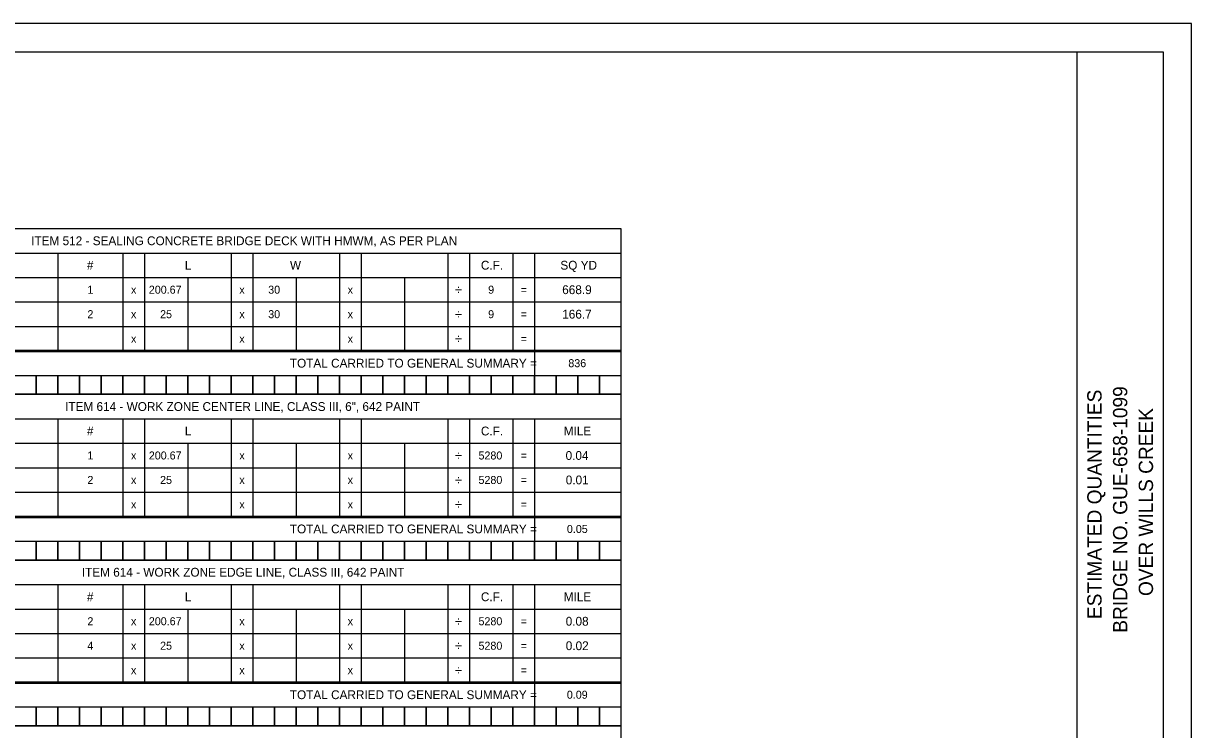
# Model space of a CAD drawing. Extents: x 0 to 34, y 0 to 22.
# Drawn here: x 13.57 to 34, y 9.65 to 22 of the extents above; entities that cross this region are included whole.
import ezdxf

# ---------------------------------------------------------------- set-up
doc = ezdxf.new("R2010")
doc.units = 0
for name, color, linetype in [('Default', 7, 'Continuous'), ('SH_Border', 7, 'Continuous'), ('SH_Cut_Line', 7, 'Continuous'), ('SH_Data', 7, 'Continuous')]:
    doc.layers.add(name, color=color, linetype=linetype)

msp = doc.modelspace()

# ---------------------------------------------------------------- linework, layer by layer
at = {"layer": 'Default'}
for p, q in [((10.763, 18.412), (24.021, 18.412)), ((24.021, 18.412), (24.021, 16.26)), ((10.763, 17.984), (24.021, 17.984)), ((14.172, 17.984), (14.172, 16.282)), ((15.308, 17.984), (15.308, 16.282)), ((15.687, 17.984), (15.687, 16.282)), ((17.203, 17.984), (17.203, 16.282)), ((17.581, 17.984), (17.581, 16.282)), ((19.097, 17.984), (19.097, 16.282)), ((19.476, 17.984), (19.476, 16.282)), ((20.991, 17.984), (20.991, 16.282)), ((21.37, 17.984), (21.37, 16.282)), ((22.127, 17.984), (22.127, 16.282)), ((22.506, 17.984), (22.506, 16.282)), ((10.763, 17.556), (24.021, 17.556)), ((16.445, 17.556), (16.445, 16.282)), ((18.339, 17.556), (18.339, 16.282)), ((20.233, 17.556), (20.233, 16.282)), ((10.763, 17.128), (24.021, 17.128)), ((10.763, 16.699), (24.021, 16.699)), ((10.763, 16.282), (24.021, 16.282)), ((10.763, 16.26), (24.021, 16.26)), ((22.506, 16.26), (22.506, 15.843)), ((24.021, 16.282), (24.021, 13.361)), ((10.763, 15.843), (24.021, 15.843)), ((10.763, 15.514), (24.021, 15.514)), ((10.763, 15.085), (24.021, 15.085)), ((14.172, 15.085), (14.172, 13.383)), ((15.308, 15.085), (15.308, 13.383)), ((15.687, 15.085), (15.687, 13.383)), ((17.203, 15.085), (17.203, 13.383)), ((17.581, 15.085), (17.581, 13.383)), ((19.097, 15.085), (19.097, 13.383)), ((19.476, 15.085), (19.476, 13.383)), ((20.991, 15.085), (20.991, 13.383)), ((21.37, 15.085), (21.37, 13.383)), ((22.127, 15.085), (22.127, 13.383)), ((22.506, 15.085), (22.506, 13.383)), ((10.763, 14.657), (24.021, 14.657)), ((16.445, 14.657), (16.445, 13.383)), ((18.339, 14.657), (18.339, 13.383)), ((20.233, 14.657), (20.233, 13.383)), ((10.763, 14.229), (24.021, 14.229)), ((10.763, 13.801), (24.021, 13.801)), ((10.763, 13.383), (24.021, 13.383)), ((10.763, 13.361), (24.021, 13.361)), ((22.506, 13.361), (22.506, 12.944)), ((24.021, 13.383), (24.021, 10.463)), ((10.763, 12.944), (24.021, 12.944)), ((10.763, 12.615), (24.021, 12.615)), ((10.763, 12.187), (24.021, 12.187)), ((14.172, 12.187), (14.172, 10.485)), ((15.308, 12.187), (15.308, 10.485)), ((15.687, 12.187), (15.687, 10.485)), ((17.203, 12.187), (17.203, 10.485)), ((17.581, 12.187), (17.581, 10.485)), ((19.097, 12.187), (19.097, 10.485)), ((19.476, 12.187), (19.476, 10.485)), ((20.991, 12.187), (20.991, 10.485)), ((21.37, 12.187), (21.37, 10.485)), ((22.127, 12.187), (22.127, 10.485)), ((22.506, 12.187), (22.506, 10.485)), ((10.763, 11.758), (24.021, 11.758)), ((16.445, 11.758), (16.445, 10.485)), ((18.339, 11.758), (18.339, 10.485)), ((20.233, 11.758), (20.233, 10.485)), ((10.763, 11.33), (24.021, 11.33)), ((10.763, 10.902), (24.021, 10.902)), ((10.763, 10.485), (24.021, 10.485)), ((10.763, 10.463), (24.021, 10.463)), ((22.506, 10.463), (22.506, 10.045)), ((24.021, 10.485), (24.021, 7.564)), ((10.763, 10.045), (24.021, 10.045)), ((10.763, 9.716), (24.021, 9.716))]:
    msp.add_line(p, q, dxfattribs=at)
for points in [[(13.414, 15.843), (13.793, 15.843), (13.793, 15.514), (13.414, 15.514)], [(13.793, 15.843), (14.172, 15.843), (14.172, 15.514), (13.793, 15.514)], [(14.172, 15.843), (14.551, 15.843), (14.551, 15.514), (14.172, 15.514)], [(14.551, 15.843), (14.93, 15.843), (14.93, 15.514), (14.551, 15.514)], [(14.93, 15.843), (15.308, 15.843), (15.308, 15.514), (14.93, 15.514)], [(15.308, 15.843), (15.687, 15.843), (15.687, 15.514), (15.308, 15.514)], [(15.687, 15.843), (16.066, 15.843), (16.066, 15.514), (15.687, 15.514)], [(16.066, 15.843), (16.445, 15.843), (16.445, 15.514), (16.066, 15.514)], [(16.445, 15.843), (16.824, 15.843), (16.824, 15.514), (16.445, 15.514)], [(16.824, 15.843), (17.203, 15.843), (17.203, 15.514), (16.824, 15.514)], [(17.203, 15.843), (17.581, 15.843), (17.581, 15.514), (17.203, 15.514)], [(17.581, 15.843), (17.96, 15.843), (17.96, 15.514), (17.581, 15.514)], [(17.96, 15.843), (18.339, 15.843), (18.339, 15.514), (17.96, 15.514)], [(18.339, 15.843), (18.718, 15.843), (18.718, 15.514), (18.339, 15.514)], [(18.718, 15.843), (19.097, 15.843), (19.097, 15.514), (18.718, 15.514)], [(19.097, 15.843), (19.476, 15.843), (19.476, 15.514), (19.097, 15.514)], [(19.476, 15.843), (19.854, 15.843), (19.854, 15.514), (19.476, 15.514)], [(19.854, 15.843), (20.233, 15.843), (20.233, 15.514), (19.854, 15.514)], [(20.233, 15.843), (20.612, 15.843), (20.612, 15.514), (20.233, 15.514)], [(20.612, 15.843), (20.991, 15.843), (20.991, 15.514), (20.612, 15.514)], [(20.991, 15.843), (21.37, 15.843), (21.37, 15.514), (20.991, 15.514)], [(21.37, 15.843), (21.748, 15.843), (21.748, 15.514), (21.37, 15.514)], [(21.748, 15.843), (22.127, 15.843), (22.127, 15.514), (21.748, 15.514)], [(22.127, 15.843), (22.506, 15.843), (22.506, 15.514), (22.127, 15.514)], [(22.506, 15.843), (22.885, 15.843), (22.885, 15.514), (22.506, 15.514)], [(22.885, 15.843), (23.264, 15.843), (23.264, 15.514), (22.885, 15.514)], [(23.264, 15.843), (23.643, 15.843), (23.643, 15.514), (23.264, 15.514)], [(23.643, 15.843), (24.021, 15.843), (24.021, 15.514), (23.643, 15.514)], [(13.414, 12.944), (13.793, 12.944), (13.793, 12.615), (13.414, 12.615)], [(13.793, 12.944), (14.172, 12.944), (14.172, 12.615), (13.793, 12.615)], [(14.172, 12.944), (14.551, 12.944), (14.551, 12.615), (14.172, 12.615)], [(14.551, 12.944), (14.93, 12.944), (14.93, 12.615), (14.551, 12.615)], [(14.93, 12.944), (15.308, 12.944), (15.308, 12.615), (14.93, 12.615)], [(15.308, 12.944), (15.687, 12.944), (15.687, 12.615), (15.308, 12.615)], [(15.687, 12.944), (16.066, 12.944), (16.066, 12.615), (15.687, 12.615)], [(16.066, 12.944), (16.445, 12.944), (16.445, 12.615), (16.066, 12.615)], [(16.445, 12.944), (16.824, 12.944), (16.824, 12.615), (16.445, 12.615)], [(16.824, 12.944), (17.203, 12.944), (17.203, 12.615), (16.824, 12.615)], [(17.203, 12.944), (17.581, 12.944), (17.581, 12.615), (17.203, 12.615)], [(17.581, 12.944), (17.96, 12.944), (17.96, 12.615), (17.581, 12.615)], [(17.96, 12.944), (18.339, 12.944), (18.339, 12.615), (17.96, 12.615)], [(18.339, 12.944), (18.718, 12.944), (18.718, 12.615), (18.339, 12.615)], [(18.718, 12.944), (19.097, 12.944), (19.097, 12.615), (18.718, 12.615)], [(19.097, 12.944), (19.476, 12.944), (19.476, 12.615), (19.097, 12.615)], [(19.476, 12.944), (19.854, 12.944), (19.854, 12.615), (19.476, 12.615)], [(19.854, 12.944), (20.233, 12.944), (20.233, 12.615), (19.854, 12.615)], [(20.233, 12.944), (20.612, 12.944), (20.612, 12.615), (20.233, 12.615)], [(20.612, 12.944), (20.991, 12.944), (20.991, 12.615), (20.612, 12.615)], [(20.991, 12.944), (21.37, 12.944), (21.37, 12.615), (20.991, 12.615)], [(21.37, 12.944), (21.748, 12.944), (21.748, 12.615), (21.37, 12.615)], [(21.748, 12.944), (22.127, 12.944), (22.127, 12.615), (21.748, 12.615)], [(22.127, 12.944), (22.506, 12.944), (22.506, 12.615), (22.127, 12.615)], [(22.506, 12.944), (22.885, 12.944), (22.885, 12.615), (22.506, 12.615)], [(22.885, 12.944), (23.264, 12.944), (23.264, 12.615), (22.885, 12.615)], [(23.264, 12.944), (23.643, 12.944), (23.643, 12.615), (23.264, 12.615)], [(23.643, 12.944), (24.021, 12.944), (24.021, 12.615), (23.643, 12.615)], [(13.414, 10.045), (13.793, 10.045), (13.793, 9.716), (13.414, 9.716)], [(13.793, 10.045), (14.172, 10.045), (14.172, 9.716), (13.793, 9.716)], [(14.172, 10.045), (14.551, 10.045), (14.551, 9.716), (14.172, 9.716)], [(14.551, 10.045), (14.93, 10.045), (14.93, 9.716), (14.551, 9.716)], [(14.93, 10.045), (15.308, 10.045), (15.308, 9.716), (14.93, 9.716)], [(15.308, 10.045), (15.687, 10.045), (15.687, 9.716), (15.308, 9.716)], [(15.687, 10.045), (16.066, 10.045), (16.066, 9.716), (15.687, 9.716)], [(16.066, 10.045), (16.445, 10.045), (16.445, 9.716), (16.066, 9.716)], [(16.445, 10.045), (16.824, 10.045), (16.824, 9.716), (16.445, 9.716)], [(16.824, 10.045), (17.203, 10.045), (17.203, 9.716), (16.824, 9.716)], [(17.203, 10.045), (17.581, 10.045), (17.581, 9.716), (17.203, 9.716)], [(17.581, 10.045), (17.96, 10.045), (17.96, 9.716), (17.581, 9.716)], [(17.96, 10.045), (18.339, 10.045), (18.339, 9.716), (17.96, 9.716)], [(18.339, 10.045), (18.718, 10.045), (18.718, 9.716), (18.339, 9.716)], [(18.718, 10.045), (19.097, 10.045), (19.097, 9.716), (18.718, 9.716)], [(19.097, 10.045), (19.476, 10.045), (19.476, 9.716), (19.097, 9.716)], [(19.476, 10.045), (19.854, 10.045), (19.854, 9.716), (19.476, 9.716)], [(19.854, 10.045), (20.233, 10.045), (20.233, 9.716), (19.854, 9.716)], [(20.233, 10.045), (20.612, 10.045), (20.612, 9.716), (20.233, 9.716)], [(20.612, 10.045), (20.991, 10.045), (20.991, 9.716), (20.612, 9.716)], [(20.991, 10.045), (21.37, 10.045), (21.37, 9.716), (20.991, 9.716)], [(21.37, 10.045), (21.748, 10.045), (21.748, 9.716), (21.37, 9.716)], [(21.748, 10.045), (22.127, 10.045), (22.127, 9.716), (21.748, 9.716)], [(22.127, 10.045), (22.506, 10.045), (22.506, 9.716), (22.127, 9.716)], [(22.506, 10.045), (22.885, 10.045), (22.885, 9.716), (22.506, 9.716)], [(22.885, 10.045), (23.264, 10.045), (23.264, 9.716), (22.885, 9.716)], [(23.264, 10.045), (23.643, 10.045), (23.643, 9.716), (23.264, 9.716)], [(23.643, 10.045), (24.021, 10.045), (24.021, 9.716), (23.643, 9.716)]]:
    msp.add_lwpolyline(points, close=True, dxfattribs=at)
at = {"layer": 'SH_Border'}
msp.add_line((32, 0.5), (32, 21.5), dxfattribs=at)
msp.add_lwpolyline([(1.5, 21.5), (33.5, 21.5), (33.5, 0.5), (1.5, 0.5)], close=True, dxfattribs=at)
at = {"layer": 'SH_Cut_Line'}
msp.add_lwpolyline([(0, 0), (34, 0), (34, 22), (0, 22)], close=True, dxfattribs=at)

# ---------------------------------------------------------------- texts
at = {"layer": 'Default'}
for s, height, p in [('ITEM 512 - SEALING CONCRETE BRIDGE DECK WITH HMWM, AS PER PLAN', 0.154, (13.707, 18.121)), ('#', 0.154, (14.682, 17.693)), ('L', 0.154, (16.394, 17.693)), ('W', 0.154, (18.232, 17.693)), ('C.F.', 0.154, (21.571, 17.693)), ('SQ YD', 0.154, (22.961, 17.693)), ('1', 0.14, (14.69, 17.272)), ('x', 0.14, (15.452, 17.272)), ('200.67', 0.14, (15.764, 17.272)), ('x', 0.14, (17.347, 17.272)), ('30', 0.14, (17.852, 17.272)), ('x', 0.14, (19.241, 17.272)), ('÷', 0.168, (21.118, 17.258)), ('9', 0.14, (21.698, 17.272)), ('=', 0.14, (22.267, 17.272)), ('668.9', 0.154, (22.993, 17.265)), ('2', 0.14, (14.69, 16.844)), ('25', 0.14, (15.961, 16.844)), ('30', 0.14, (17.852, 16.844)), ('÷', 0.168, (21.118, 16.83)), ('9', 0.14, (21.698, 16.844)), ('166.7', 0.154, (22.993, 16.837)), ('x', 0.14, (15.452, 16.844)), ('x', 0.14, (17.347, 16.844)), ('x', 0.14, (19.241, 16.844)), ('=', 0.14, (22.267, 16.844)), ('x', 0.14, (15.452, 16.415)), ('x', 0.14, (17.347, 16.415)), ('x', 0.14, (19.241, 16.415)), ('÷', 0.168, (21.118, 16.401)), ('=', 0.14, (22.267, 16.415)), ('TOTAL CARRIED TO GENERAL SUMMARY =', 0.154, (18.23, 15.98)), ('836', 0.14, (23.1, 15.987)), ('ITEM 614 - WORK ZONE CENTER LINE, CLASS III, 6", 642 PAINT', 0.154, (14.3, 15.222)), ('#', 0.154, (14.682, 14.794)), ('L', 0.154, (16.394, 14.794)), ('C.F.', 0.154, (21.571, 14.794)), ('MILE', 0.154, (23.02, 14.794)), ('1', 0.14, (14.69, 14.373)), ('200.67', 0.14, (15.764, 14.373)), ('5280', 0.14, (21.529, 14.373)), ('0.04', 0.154, (23.052, 14.366)), ('x', 0.14, (15.452, 14.373)), ('x', 0.14, (17.347, 14.373)), ('x', 0.14, (19.241, 14.373)), ('÷', 0.168, (21.118, 14.359)), ('=', 0.14, (22.267, 14.373)), ('2', 0.14, (14.69, 13.945)), ('x', 0.14, (15.452, 13.945)), ('25', 0.14, (15.961, 13.945)), ('x', 0.14, (17.347, 13.945)), ('x', 0.14, (19.241, 13.945)), ('÷', 0.168, (21.118, 13.931)), ('5280', 0.14, (21.529, 13.945)), ('=', 0.14, (22.267, 13.945)), ('0.01', 0.154, (23.055, 13.938)), ('x', 0.14, (15.452, 13.517)), ('x', 0.14, (17.347, 13.517)), ('x', 0.14, (19.241, 13.517)), ('÷', 0.168, (21.118, 13.503)), ('=', 0.14, (22.267, 13.517)), ('TOTAL CARRIED TO GENERAL SUMMARY =', 0.154, (18.23, 13.081)), ('0.05', 0.14, (23.075, 13.088)), ('ITEM 614 - WORK ZONE EDGE LINE, CLASS III, 642 PAINT', 0.154, (14.592, 12.324)), ('#', 0.154, (14.682, 11.895)), ('L', 0.154, (16.394, 11.895)), ('C.F.', 0.154, (21.571, 11.895)), ('MILE', 0.154, (23.02, 11.895)), ('2', 0.14, (14.69, 11.474)), ('x', 0.14, (15.452, 11.474)), ('200.67', 0.14, (15.764, 11.474)), ('x', 0.14, (17.347, 11.474)), ('x', 0.14, (19.241, 11.474)), ('÷', 0.168, (21.118, 11.46)), ('5280', 0.14, (21.529, 11.474)), ('=', 0.14, (22.267, 11.474)), ('0.08', 0.154, (23.054, 11.467)), ('4', 0.14, (14.688, 11.046)), ('x', 0.14, (15.452, 11.046)), ('25', 0.14, (15.961, 11.046)), ('x', 0.14, (17.347, 11.046)), ('x', 0.14, (19.241, 11.046)), ('÷', 0.168, (21.118, 11.032)), ('5280', 0.14, (21.529, 11.046)), ('=', 0.14, (22.267, 11.046)), ('0.02', 0.154, (23.055, 11.039)), ('x', 0.14, (15.452, 10.618)), ('x', 0.14, (17.347, 10.618)), ('x', 0.14, (19.241, 10.618)), ('÷', 0.168, (21.118, 10.604)), ('=', 0.14, (22.267, 10.618)), ('TOTAL CARRIED TO GENERAL SUMMARY =', 0.154, (18.23, 10.182)), ('0.09', 0.14, (23.074, 10.189))]:
    msp.add_text(s, height=height, dxfattribs=at).set_placement(p)
at = {"layer": 'SH_Data'}
for s, p in [('ESTIMATED QUANTITIES', (32.425, 11.582)), ('BRIDGE NO. GUE-658-1099', (32.875, 11.343)), ('OVER WILLS CREEK', (33.325, 11.985))]:
    msp.add_text(s, height=0.25, rotation=90, dxfattribs=at).set_placement(p)

doc.saveas('drawing.dxf')
